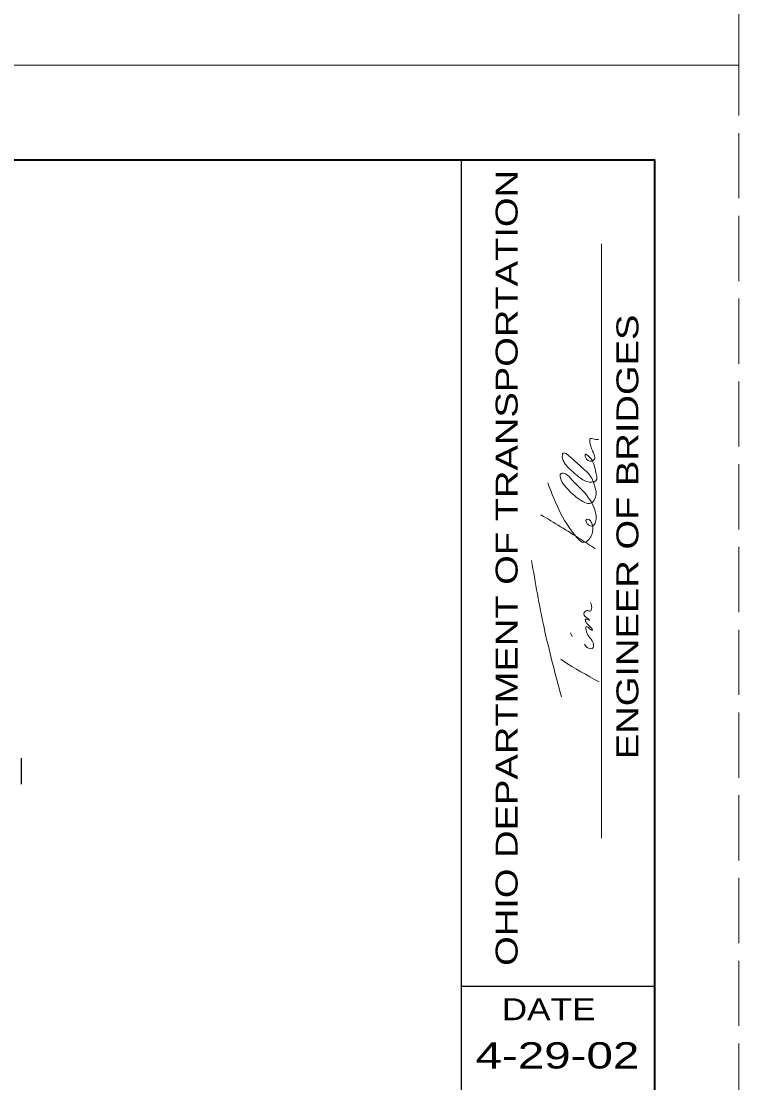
# Model space of a CAD drawing. Extents: x 1083.1 to 1117.1, y 672.5 to 716.5.
# Drawn here: x 1113.04 to 1117.13, y 688.7 to 694.76 of the extents above; entities that cross this region are included whole.
import ezdxf
from ezdxf.enums import TextEntityAlignment as Align

# ---------------------------------------------------------------- set-up
doc = ezdxf.new("R2010")
doc.units = 0
doc.header["$LTSCALE"] = 0.062
doc.linetypes.add('LONG_DASHED', pattern=[7.5, 6, -1.5])
doc.layers.add('1', color=7, linetype='Continuous', lineweight=13)

msp = doc.modelspace()

# ---------------------------------------------------------------- linework, layer by layer
at = {"layer": '1', "lineweight": 25}
for p, q in [((1085.14617, 693.96842), (1116.64617, 693.96842)), ((1115.54617, 672.96842), (1115.54617, 693.96842)), ((1116.64617, 693.96842), (1116.64617, 672.96842)), ((1113.03933, 690.40717), (1113.03933, 690.55467)), ((1116.64617, 689.25258), (1115.54617, 689.25258))]:
    msp.add_line(p, q, dxfattribs=at)
at = {"layer": '1'}
for p, q in [((1116.34492, 690.09942), (1116.34492, 693.4895)), ((1116.17742, 691.25033), (1116.16725, 691.26958))]:
    msp.add_line(p, q, dxfattribs=at)
at = {"layer": '1', "linetype": 'LONG_DASHED'}
for points in [[(1083.12642, 694.50825), (1117.12642, 694.50825), (1117.12642, 716.50825), (1083.12642, 716.50825)], [(1083.12642, 672.50825), (1117.12642, 672.50825), (1117.12642, 694.50825), (1083.12642, 694.50825)]]:
    msp.add_lwpolyline(points, close=True, dxfattribs=at)
at = {"layer": '1', "lineweight": 40}
msp.add_lwpolyline([(1085.14617, 693.96842), (1116.64617, 693.96842), (1116.64617, 672.96842), (1085.14617, 672.96842)], close=True, dxfattribs=at)
at = {"layer": '1'}
for points in [[(1116.038, 692.12542), (1116.22117, 691.79708), (1116.23633, 691.7865), (1116.2465, 691.7865), (1116.27842, 691.81017), (1116.2935, 691.84433), (1116.2885, 691.89558), (1116.27158, 691.91742), (1116.25808, 691.91742), (1116.25633, 691.90442), (1116.2665, 691.88925), (1116.28, 691.88083), (1116.29508, 691.88083), (1116.31025, 691.90242), (1116.31367, 691.92175), (1116.30342, 691.97708), (1116.22117, 692.0975), (1116.17567, 692.14217), (1116.13875, 692.17675), (1116.11358, 692.17892), (1116.11533, 692.14033), (1116.1405, 692.10158), (1116.20775, 692.03925), (1116.24983, 692.01383), (1116.2835, 692.00933), (1116.30683, 692.03533), (1116.31367, 692.0695), (1116.30858, 692.09525), (1116.27842, 692.16842), (1116.24817, 692.20042), (1116.18758, 692.25383), (1116.15892, 692.27967), (1116.12542, 692.29492), (1116.122, 692.26692), (1116.13208, 692.24108), (1116.18925, 692.18117), (1116.25992, 692.13392), (1116.31192, 692.13625), (1116.31025, 692.19392), (1116.29842, 692.23683), (1116.28508, 692.26258), (1116.27492, 692.27333), (1116.2515, 692.28833), (1116.25325, 692.27125), (1116.2885, 692.24975), (1116.30342, 692.2605), (1116.29033, 692.31417), (1116.28175, 692.34208), (1116.27842, 692.35475), (1116.27842, 692.36758), (1116.27842, 692.37625), (1116.30342, 692.37408), (1116.32883, 692.37408)], [(1115.99917, 691.94317), (1116.22292, 691.80567), (1116.30858, 691.75)], [(1116.11542, 690.90617), (1116.01675, 691.30142), (1115.9455, 691.68375)], [(1116.2465, 691.20508), (1116.25475, 691.19442), (1116.29192, 691.1815), (1116.29667, 691.21392), (1116.27158, 691.25033), (1116.25633, 691.28658), (1116.25633, 691.30583), (1116.27158, 691.29958), (1116.28175, 691.28875), (1116.29192, 691.28442), (1116.26825, 691.31658), (1116.25633, 691.33158), (1116.25325, 691.34892), (1116.27667, 691.34233), (1116.26825, 691.351), (1116.24308, 691.37883), (1116.25325, 691.394), (1116.27, 691.396), (1116.27842, 691.394), (1116.2885, 691.41533), (1116.28175, 691.44325)], [(1116.33058, 690.99058), (1116.12542, 691.11058), (1116.10983, 691.121)]]:
    msp.add_spline(points, degree=3, dxfattribs=at)

# ---------------------------------------------------------------- texts
at = {"layer": '1', "width": 1.3}
for s, p in [('OHIO DEPARTMENT OF TRANSPORTATION', (1115.86608, 691.64067)), ('ENGINEER OF BRIDGES', (1116.55442, 691.81746))]:
    msp.add_text(s, height=0.125, rotation=90, dxfattribs=at).set_placement(p, align=Align.CENTER)
at = {"layer": '1'}
for s, height, width, p in [('DATE', 0.125, 1.2, (1116.04287, 689.06117)), ('4-29-02', 0.15, 1.35, (1116.09317, 688.78567))]:
    msp.add_text(s, height=height, dxfattribs=dict(at, width=width)).set_placement(p, align=Align.CENTER)

doc.saveas('drawing.dxf')
